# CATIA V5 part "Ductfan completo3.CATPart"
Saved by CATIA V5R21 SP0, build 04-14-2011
Part number: Ductfan3
Bounding box of the stored display mesh (mm): x -394.667 to 344.98, y -40 to 360, z -344.802 to 344.802
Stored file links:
  C:\Users\rodri\OneDrive\Área de Trabalho\Ductfan completo3.CATPart
  C:\Users\andre\AppData\Local\Temp\Rar$DIa18808.12376\NACA 2412 3D Aerofoil.CATPart
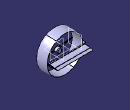
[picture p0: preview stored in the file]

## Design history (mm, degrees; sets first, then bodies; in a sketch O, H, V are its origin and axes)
Body1 (main body)
  Sketch1 on yz-plane, origin (0, 0, 0), H (0, 1, 0), V (0, 0, 1)
    point P1 (-40, -336.52)
    point P2 (160, -336.52)
    unspec C1
    unspec C2
    axis line L1 (0, -34.7251) -> (0, -104.5277)
    distance P1 P2 = 200
    distance C1 C2 = 23.9924
    distance P1 L1 = 40
    distance C1 H = 320.675
    distance P2 H = 336.52
    vertical: L1 V
    coincidence: L1 V
  Shaft1: profile Sketch1, axis Sketch1.H, angle 360
  Sketch2 on zx-plane, origin (0, 0, 0), H (-1, 0, 0), V (0, 0, 1)
    circle A1 centre (0, 0) radius 45.8
    radius A1 = 45.8
  Pad1: profile Sketch2, direction (0, 1, 0), length 60
  Fillet1: radius 10, on edge [face of Pad1 from Sketch2.A1 | end face of Pad1]
  Sketch3 on start face of Pad1, origin (0, 0, 0), H (1, 0, 0), V (0, 0, 1)
    circle A1 centre (0, 0) radius 10
    point P1 (10, 0)
    radius A1 = 10
    coincidence: A1 P1, P1 H
  Pocket1: profile Sketch3, direction (0, 1, 0), length 10
  Sketch4 on start face of Pad1, origin (0, 0, 0), H (1, 0, 0), V (0, 0, 1)
    ellipse A1 centre (0, 0) semi-axes 306.75, 10 rotation 172.047
    "Radius" A1 = 306.75
    distance A1 O = 10
  Pad2: profile Sketch4, direction (0, -1, 0), length 10
  Plane1: type Offset, RefPlane yz-plane, Offset 344.667, reversed
  Sketch5 on Plane1, origin (-344.667, 0, 0), H (0, 1, 0), V (0, 0, 1)
    point P1 (-40, -2.4533)
    point P2 (160, -2.4533)
    unspec C1
    unspec C2
    circle A1 centre (0, 0) radius 5
    point P3 (0, 0)
    circle A2 centre (60.03, -0.0038) radius 5
    point P4 (60.03, -0.0038)
    distance P1 P2 = 200
    distance P1 V = 40
    radius A1 = 5
    distance C1 C2 = 23.9924
    distance P3 C1 = 11.996
    distance P3 P1 = 40.0752
    radius A2 = 5
    distance P4 P2 = 100
    distance P4 C1 = 11.996
    distance P3 H = 0
    coincidence: P3 V
  Pad3: profile Sketch5, direction (-1, 0, 0), length 50
  Sketch6 on yz-plane, origin (0, 0, 0), H (0, 1, 0), V (0, 0, 1)
    point P1 (160, -0.1822)
    unspec C1
    unspec C2
    point P3 (26.5548, 0)
    point P4 (180, 2)
    circle A1 centre (180, 2) radius 5
    point P5 (184.5826, 0)
    line L1 (190, 11) -> (196, 11)
    line L2 (196, 11) -> (196, -6)
    line L3 (196, -6) -> (190, -6)
    line L4 (190, -6) -> (190, 11)
    point P10 (210, 3)
    circle A2 centre (210, 3) radius 7.5
    point P11 (235, 4)
    circle A3 centre (235, 4) radius 7.5
    point P12 (260, 4)
    circle A4 centre (260, 4) radius 7.5
    point P13 (285, 3)
    circle A5 centre (285, 3) radius 5
    line L5 (300, 8) -> (304, 8)
    line L6 (304, 8) -> (304, -2)
    line L7 (304, -2) -> (300, -2)
    line L8 (300, -2) -> (300, 8)
    radius A1 = 5
    distance H P4 = 2
    distance V P4 = 180
    distance L4 L2 = 6
    distance L1 L3 = 17
    distance L3 H = 6
    distance L4 V = 190
    radius A2 = 7.5
    distance P10 H = 3
    distance P10 V = 210
    radius A3 = 7.5
    distance P11 H = 4
    radius A4 = 7.5
    distance P11 V = 235
    distance P12 H = 4
    distance P12 V = 260
    radius A5 = 5
    distance P13 H = 3
    distance P13 V = 285
    distance L5 L7 = 10
    distance L8 L6 = 4
    distance L8 V = 300
    distance L7 H = 2
    distance P1 V = 160
    coincidence: A1 P5, P5 H
    horizontal: L1 H, L3 H, L5 H, L7 H
    vertical: L2 V, L4 V, L6 V, L8 V
  Pad4: profile Sketch6, direction (1, 0, 0), length 336.52, mirrored extent
  Sketch7 on end face of Pad4, origin (336.52, 0, 0), H (0, 1, 0), V (0, 0, 1)
    point P2 (360, 0)
    unspec C1
    unspec C2
    distance P2 V = 360
  Pad5: profile Sketch7, direction (1, 0, 0), length 5
  Fillet2: radius 2, on end face of Pad5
